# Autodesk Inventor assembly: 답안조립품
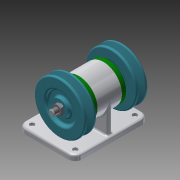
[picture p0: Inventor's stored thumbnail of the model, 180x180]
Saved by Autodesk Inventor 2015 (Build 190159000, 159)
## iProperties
Created: 2019-09
Part Number: 답안조립품
Document SubType Name: Assembly
Designer: CAD-08
Author: CAD-08
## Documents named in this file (10)
- C:\Users\CAD-08\Desktop\시험\답안조립품.iam
- C:\Users\CAD-08\Desktop\시험\V-벨트풀리.ipt
- C:\Users\CAD-08\Desktop\시험\너트 M10x1.ipt
- C:\Users\CAD-08\Desktop\시험\베어링 6004.ipt
- C:\Users\CAD-08\Desktop\시험\본체.ipt
- C:\Users\CAD-08\Desktop\시험\볼트 M4.ipt
- C:\Users\CAD-08\Desktop\시험\오일 실 17 30 5.ipt
- C:\Users\CAD-08\Desktop\시험\축.ipt
- C:\Users\CAD-08\Desktop\시험\커버.ipt
- C:\Users\CAD-08\Desktop\시험\키 5 x 5 x 12.ipt
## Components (2 placed, 1 different names)
1. V-벨트풀리:1 — 각도:3
2. V-벨트풀리:2 — 각도:4
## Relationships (2: Angle 2)
- 각도:3 [Angle]: V-벨트풀리:1
- 각도:4 [Angle]: V-벨트풀리:2
